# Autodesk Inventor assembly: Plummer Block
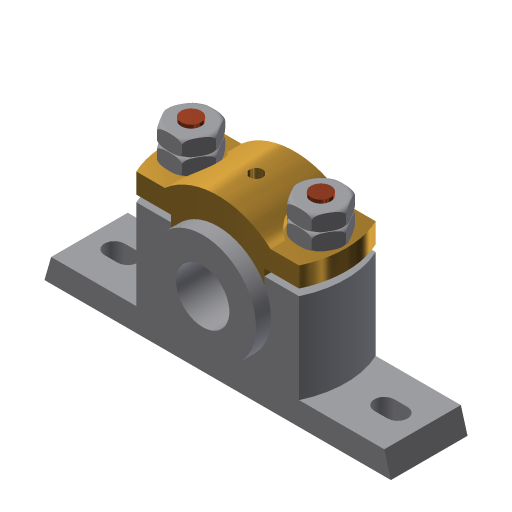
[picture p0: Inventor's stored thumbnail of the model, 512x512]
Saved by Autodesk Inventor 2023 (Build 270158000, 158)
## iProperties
Created: 2011-07
Part Number: Plummer Block
Document SubType Name: Assembly
Designer: CadCim
Author: CadCim
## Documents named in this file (7)
- D:\PROJECTS\Project 2022\Autodesk Inventor For Professional 2023\RESOURCES INVENTOR 2023\RESOURCES INVENTOR 2023\Inventor_2023_Part\Inventor_2023_Part\c11_Inv_2023_prt\c11_Inv_2023_prt\figure-11-23 through 11-26\Plummer Block.iam
- D:\PROJECTS\Project 2022\Autodesk Inventor For Professional 2023\RESOURCES INVENTOR 2023\RESOURCES INVENTOR 2023\Inventor_2023_Part\Inventor_2023_Part\c11_Inv_2023_prt\c11_Inv_2023_prt\figure-11-23 through 11-26\Casting.ipt
- D:\PROJECTS\Project 2022\Autodesk Inventor For Professional 2023\RESOURCES INVENTOR 2023\RESOURCES INVENTOR 2023\Inventor_2023_Part\Inventor_2023_Part\c11_Inv_2023_prt\c11_Inv_2023_prt\figure-11-23 through 11-26\Brasses.ipt
- D:\PROJECTS\Project 2022\Autodesk Inventor For Professional 2023\RESOURCES INVENTOR 2023\RESOURCES INVENTOR 2023\Inventor_2023_Part\Inventor_2023_Part\c11_Inv_2023_prt\c11_Inv_2023_prt\figure-11-23 through 11-26\Cap.ipt
- D:\PROJECTS\Project 2022\Autodesk Inventor For Professional 2023\RESOURCES INVENTOR 2023\RESOURCES INVENTOR 2023\Inventor_2023_Part\Inventor_2023_Part\c11_Inv_2023_prt\c11_Inv_2023_prt\figure-11-23 through 11-26\Bolt.ipt
- D:\PROJECTS\Project 2022\Autodesk Inventor For Professional 2023\RESOURCES INVENTOR 2023\RESOURCES INVENTOR 2023\Inventor_2023_Part\Inventor_2023_Part\c11_Inv_2023_prt\c11_Inv_2023_prt\figure-11-23 through 11-26\Nut.ipt
- D:\PROJECTS\Project 2022\Autodesk Inventor For Professional 2023\RESOURCES INVENTOR 2023\RESOURCES INVENTOR 2023\Inventor_2023_Part\Inventor_2023_Part\c11_Inv_2023_prt\c11_Inv_2023_prt\figure-11-23 through 11-26\Lock Nut.ipt
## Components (9 placed, 6 different names)
1. Casting:1 — Mate:1, Mate:2, Insert:1, Insert:2, Angle:1, Angle:2
2. Brasses:1 — Mate:1, Mate:2, Mate:3, Mate:4
3. Cap:1 — Mate:3, Mate:4, Insert:3, Insert:4
4. Bolt:1 — Insert:1, Angle:1
5. Bolt:2 — Insert:2, Angle:2
6. Nut:1 — Insert:3, Insert:6
7. Nut:2 — Insert:4, Insert:5
8. Lock Nut:1 — Insert:6
9. Lock Nut:2 — Insert:5
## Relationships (12: Insert 6, Mate 4, Angle 2)
- Mate:1: Casting:1 ↔ Brasses:1
- Mate:2: Casting:1 ↔ Brasses:1
- Mate:3: Brasses:1 ↔ Cap:1
- Mate:4: Brasses:1 ↔ Cap:1
- Insert:1: Casting:1 ↔ Bolt:1
- Insert:2: Casting:1 ↔ Bolt:2
- Angle:1: Casting:1 ↔ Bolt:1
- Angle:2: Casting:1 ↔ Bolt:2
- Insert:3: Cap:1 ↔ Nut:1
- Insert:4: Cap:1 ↔ Nut:2
- Insert:5: Nut:2 ↔ Lock Nut:2
- Insert:6: Nut:1 ↔ Lock Nut:1
